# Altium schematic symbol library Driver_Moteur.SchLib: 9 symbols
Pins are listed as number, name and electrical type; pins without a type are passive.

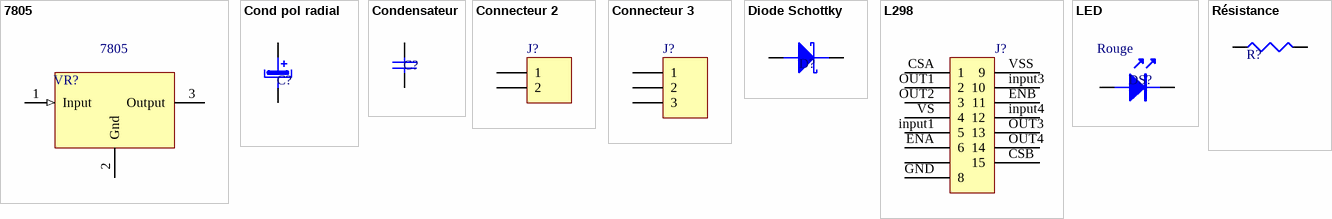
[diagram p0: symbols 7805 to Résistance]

## 7805
designator VR?  Type: 7805
Régulateur 5V
footprint TO-220 V (TO-220 Vertical)
pins: 1 Input (in), 2 Gnd (power), 3 Output (power)

## Cond pol radial
designator C?
Condensateur polatisé; Type: Condensateur polarisé debout
footprint CAPPR2-5x6.8 (Capacitor, Electrolytic, Radial; Body 5 x 6.8 mm (Dia.xH typ); Pin Spacing 2 mm (typ))
pins: 1 +, 2 -
2 alternate drawings of the same symbol

## Condensateur
designator C?
Condensateur
footprint CAPR5.08-7.8x3.2 (Capacitor, Ceramic, Thru-Hole, Dipped Radial; Body 7.8 x 3.2 mm (WxT) Pin Spacing 5.08 mm (typ))
pins: 1, 2

## Connecteur 2
designator J?
Connecteur
footprint CONVIS-2 (Connecteur à vis 2 contacts Pitch 5.08)
pins: 1, 2

## Connecteur 3
designator J?
Connecteur
footprint CONVIS-3 (Connecteur à vis 3 contacts Pitch 5.08)
footprint HDR1X3 (Connector; Header; 3 Position)
pins: 1, 2, 3

## Diode Schottky
designator D?
Diode Schottky
footprint DIODE-0.4 (Tunnel Diode - Dependent Source Model; 2 Leads)
pins: 1 A, 2 K

## L298
designator J?
Connecteur
footprint MultiWatt15 (MultiWatt15; 15 Leads; Row Spacing 5.08 mm; Pitch 2.54 mm)
pins: CSA 1, CSB 15, ENA 6, ENB 11, GND 8, input1 5, input2 7, input3 10, input4 12, OUT1 2, OUT2 3, OUT3 13, OUT4 14, VS 4, VSS 9

## LED
designator DS?  Color: Rouge
LED
footprint Led 0.1 (Led Verticale)
pins: 1 A, 2 K

## Résistance
designator R?
Résistance standard
footprint AXIAL-0.4 (Resistor; 2 Leads)
pins: 1, 2
3 alternate drawings of the same symbol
